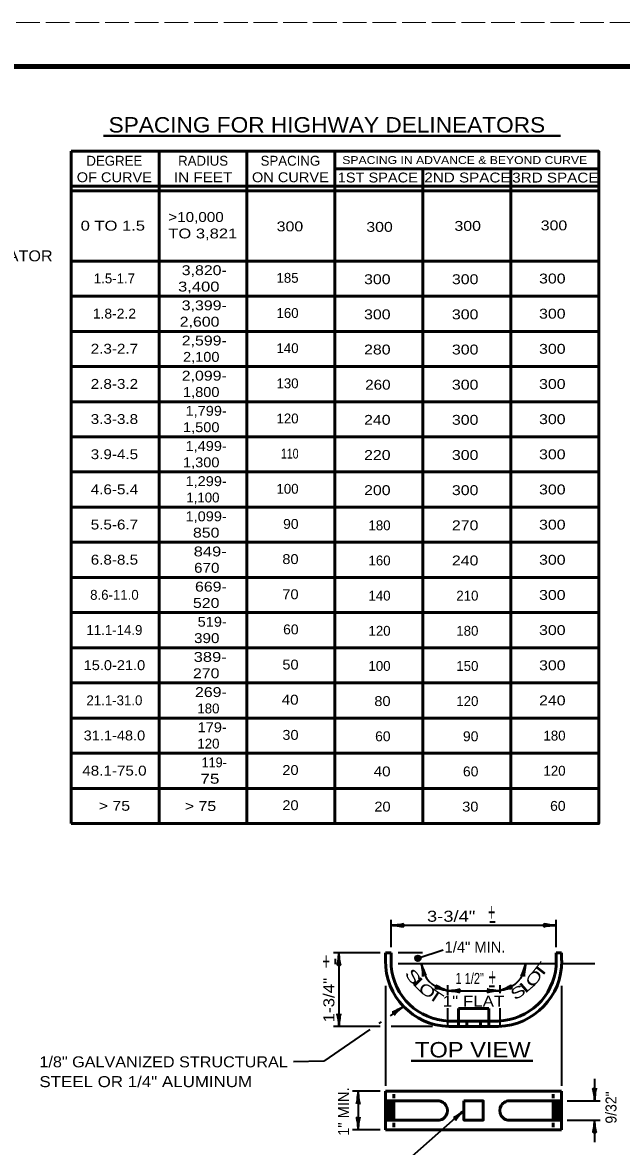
# Model space of a CAD drawing. Extents: x -54 to 626, y -41 to 399.
# Drawn here: x 331.9 to 468.1, y 142.9 to 398.7 of the extents above; entities that cross this region are included whole.
import ezdxf
from ezdxf.enums import TextEntityAlignment as Align

# ---------------------------------------------------------------- set-up
doc = ezdxf.new("R2010")
doc.units = 0
doc.header["$LTSCALE"] = 0.9
doc.linetypes.add('LONG_DASHED', pattern=[7.5, 6, -1.5])
doc.linetypes.add('MEDIUM_DASHED', pattern=[4.5, 3, -1.5])
doc.layers.add('1', color=7, linetype='Continuous', lineweight=35)
doc.layers.add('61', color=7, linetype='Continuous', lineweight=35)

msp = doc.modelspace()

# ---------------------------------------------------------------- hatches: boundary and pattern name
at = {"layer": '1'}
msp.add_hatch(color=256, dxfattribs=at).paths.add_polyline_path([(422.3962, 185.7724, 1), (421.1462, 185.7724, 1)])

# ---------------------------------------------------------------- linework, layer by layer
at = {"layer": '1', "lineweight": 40}
for p, q in [((350.2797, 372.8977), (454.1692, 372.8977)), ((420.1955, 162.4636), (447.8977, 162.4636))]:
    msp.add_line(p, q, dxfattribs=at)
at = {"layer": '1', "lineweight": 53}
for p, q in [((342.8963, 360.4209), (342.8963, 369.4209)), ((362.8963, 216.4209), (362.8963, 369.4209)), ((382.8963, 216.4209), (382.8963, 369.4209)), ((402.8963, 216.4209), (402.8963, 369.4209)), ((402.8963, 365.4209), (462.8963, 365.4209)), ((422.8963, 216.4209), (422.8963, 365.4209)), ((442.8963, 216.4209), (442.8963, 365.4209)), ((342.8963, 361.4209), (462.8963, 361.4209)), ((342.8963, 360.4209), (462.8963, 360.4209)), ((342.8963, 344.4209), (462.8963, 344.4209)), ((342.8963, 336.4209), (462.8963, 336.4209)), ((342.8963, 328.4209), (462.8963, 328.4209)), ((342.8963, 320.4209), (462.8963, 320.4209)), ((342.8963, 312.4209), (462.8963, 312.4209)), ((342.8963, 304.4209), (462.8963, 304.4209)), ((342.8963, 296.4209), (462.8963, 296.4209)), ((342.8963, 288.4209), (462.8963, 288.4209)), ((342.8963, 280.4209), (462.8963, 280.4209)), ((342.8963, 272.4209), (462.8963, 272.4209)), ((342.8963, 264.4209), (462.8963, 264.4209)), ((342.8963, 256.4209), (462.8963, 256.4209)), ((342.8963, 248.4209), (462.8963, 248.4209)), ((342.8963, 240.4209), (462.8963, 240.4209)), ((342.8963, 232.4209), (462.8963, 232.4209)), ((342.8963, 224.4209), (462.8963, 224.4209)), ((414.4306, 187.0178), (414.4306, 185.2447)), ((414.4306, 187.0178), (415.6806, 187.0178)), ((415.6806, 187.0178), (415.6806, 183.9947)), ((453.1806, 187.0178), (453.1806, 183.9947)), ((453.1806, 187.0178), (454.4306, 187.0178)), ((454.4306, 187.0178), (454.4306, 185.2447)), ((430.9931, 174.3072), (430.9931, 170.2447)), ((430.9931, 174.3072), (437.8681, 174.3072)), ((437.8681, 174.3072), (437.8681, 170.2447)), ((428.8056, 171.4947), (440.0556, 171.4947)), ((428.8056, 170.2447), (440.0556, 170.2447)), ((414.4306, 155.4938), (454.4306, 155.4938)), ((414.4306, 155.4938), (414.4306, 153.3063)), ((416.3056, 154.8688), (416.3056, 153.9313)), ((452.5556, 154.8688), (452.5556, 153.9313)), ((454.4306, 155.4938), (454.4306, 153.3063)), ((414.4306, 152.9551), (414.7818, 153.3063)), ((414.4306, 152.0712), (415.6658, 153.3063)), ((414.4306, 151.1873), (416.3056, 153.0623)), ((414.4306, 150.3034), (416.3056, 152.1784)), ((414.4306, 149.4195), (416.3056, 151.2945)), ((416.3056, 153.3063), (416.3056, 148.9313)), ((416.3056, 153.3063), (425.9931, 153.3063)), ((416.3056, 153.3063), (416.3056, 148.9313)), ((452.5556, 148.9313), (452.5556, 153.3063)), ((452.5556, 153.3063), (452.5556, 148.9313)), ((454.4306, 151.1204), (452.5556, 152.9954)), ((454.4306, 150.2366), (452.5556, 152.1116)), ((454.4306, 149.3527), (452.5556, 151.2277)), ((454.4306, 152.0042), (453.1285, 153.3063)), ((454.4306, 152.8882), (454.0125, 153.3063)), ((414.4306, 148.9313), (414.4306, 146.7438)), ((425.9931, 148.9313), (414.4306, 148.9313)), ((414.8263, 148.9313), (416.3056, 150.4107)), ((415.7102, 148.9313), (416.3056, 149.5267)), ((453.968, 148.9313), (452.5556, 150.3438)), ((453.0842, 148.9313), (452.5556, 149.4599)), ((454.4306, 148.9313), (454.4306, 146.7438)), ((414.4306, 146.7438), (454.4306, 146.7438)), ((416.3056, 148.3063), (416.3056, 147.3688)), ((452.5556, 148.3063), (452.5556, 147.3688))]:
    msp.add_line(p, q, dxfattribs=at)
at = {"layer": '1'}
for p, q in [((415.6806, 188.2678), (415.6806, 194.5178)), ((453.1806, 188.2678), (453.1806, 194.5178)), ((415.6806, 193.2678), (453.1806, 193.2678)), ((413.1806, 187.0178), (402.5556, 187.0178)), ((403.8056, 187.0178), (403.8056, 170.2447)), ((417.2431, 187.0563), (422.7978, 187.0563)), ((421.7713, 185.7724), (427.4873, 187.7001)), ((417.2431, 184.5563), (453.1806, 184.5563)), ((454.4659, 184.5563), (461.9659, 184.5563)), ((414.4306, 179.5178), (414.4306, 156.7438)), ((428.4931, 179.6197), (428.4931, 177.4076)), ((440.3681, 179.6197), (440.3681, 177.8185)), ((454.4306, 179.5178), (454.4306, 156.7438)), ((428.4931, 178.3697), (440.3681, 178.3697)), ((418.5205, 174.8172), (415.46, 172.7092)), ((428.4931, 174.3814), (428.4931, 171.8072)), ((440.3681, 174.3814), (440.3681, 171.8072)), ((410.8521, 169.5355), (400.3792, 162.3222)), ((413.1806, 170.2447), (402.5556, 170.2447)), ((413.401, 171.2911), (412.9111, 170.9537)), ((425.0556, 170.2447), (415.6806, 170.2447)), ((428.4931, 171.1822), (428.4931, 170.5572)), ((440.3681, 171.1822), (440.3681, 170.5572)), ((400.3792, 162.3222), (393.5135, 162.2342)), ((461.9306, 158.3063), (461.9306, 153.3063)), ((413.1806, 155.4938), (406.9306, 155.4938)), ((408.1806, 155.4938), (408.1806, 146.7438)), ((455.6806, 153.3063), (463.1806, 153.3063)), ((455.6806, 148.9313), (463.1806, 148.9313)), ((461.9306, 148.9313), (461.9306, 143.9313)), ((413.1806, 146.7438), (406.9306, 146.7438))]:
    msp.add_line(p, q, dxfattribs=at)
at = {"layer": '1', "linetype": 'MEDIUM_DASHED', "lineweight": 53}
for p, q in [((432.8681, 171.4947), (432.8681, 170.2447)), ((435.9931, 171.4947), (435.9931, 170.2447))]:
    msp.add_line(p, q, dxfattribs=at)
at = {"layer": '1', "lineweight": 53}
for points in [[(342.8963, 369.4209), (462.8963, 369.4209), (462.8963, 216.4209), (342.8963, 216.4209)], [(342.8963, 216.4209), (342.8963, 344.4209), (342.8963, 360.4209)], [(414.4306, 148.9313), (414.4306, 153.3063), (425.9931, 153.3063)], [(425.9931, 148.9313), (416.3056, 148.9313), (416.3056, 153.3063)], [(442.8681, 153.3063), (454.4306, 153.3063), (454.4306, 148.9313), (442.8681, 148.9313)], [(442.8681, 148.9313), (452.5556, 148.9313), (452.5556, 153.3063), (442.8681, 153.3063)]]:
    msp.add_lwpolyline(points, dxfattribs=at)
at = {"layer": '1'}
msp.add_lwpolyline([(432.2431, 151.1188), (420.4005, 140.6441), (406.0473, 140.6441)], dxfattribs=at)
at = {"layer": '1', "lineweight": 53}
msp.add_lwpolyline([(432.2431, 153.3063), (432.2431, 148.9313), (436.6181, 148.9313), (436.6181, 153.3063)], close=True, dxfattribs=at)
at = {"layer": '1'}
msp.add_circle((421.7712, 185.7724), 0.625, dxfattribs=at)
at = {"layer": '1', "lineweight": 53}
for centre, radius, start, end in [((429.2552, 185.1074), 14.8701, 179.46942, 268.10829), ((439.606, 185.1074), 14.8701, 271.89171, 0.53058), ((429.2552, 185.1074), 13.6201, 184.68607, 268.10829), ((439.606, 185.1074), 13.6201, 271.89171, 355.31393), ((426.2861, 151.1189), 2.207, 262.37185, 97.62815), ((426.2861, 151.1189), 2.207, 262.37185, 97.62815), ((442.5751, 151.1189), 2.207, 82.37185, 277.62815), ((442.5751, 151.1189), 2.207, 82.37185, 277.62815)]:
    msp.add_arc(centre, radius, start, end, dxfattribs=at)
at = {"layer": '1'}
for centre, start, end in [((429.2552, 185.1074), 198.64913, 263.51251), ((439.606, 185.1074), 276.48749, 341.85662)]:
    msp.add_arc(centre, 6.7451, start, end, dxfattribs=at)
at = {"layer": '1', "lineweight": 40}
for centre, major_axis, ratio, start_param, end_param in [((416.8011, 193.0562), (-1.7565, 0.1757), 0.07063, 3.14071475, 5.41810995), ((416.7718, 193.5441), (-1.7857, -0.1562), 0.122415, 0.89635335, 3.14159265), ((452.0894, 192.9915), (1.7857, 0.1562), 0.122415, 0.89635335, 3.14159265), ((452.0894, 192.9915), (1.7857, 0.1562), 0.122415, 0.89635335, 3.14159265), ((452.0601, 193.4794), (1.7565, -0.1757), 0.07063, 3.14071475, 5.41810995), ((452.0601, 193.4794), (1.7565, -0.1757), 0.07063, 3.14071475, 5.41810995), ((403.594, 185.8973), (0.1757, 1.7565), 0.07063, 3.14071475, 5.41810995), ((403.594, 185.8973), (0.1757, 1.7565), 0.07063, 3.14071475, 5.41810995), ((404.0819, 185.9266), (-0.1562, 1.7857), 0.122415, 0.89635335, 3.14159265), ((404.0819, 185.9266), (-0.1562, 1.7857), 0.122415, 0.89635335, 3.14159265), ((422.552, 183.4241), (-0.3017, 1.7669), 0.122415, 3.14159265, 5.38683196), ((423.0314, 183.5194), (0.6152, -1.6545), 0.07063, 4.00666801, 6.28406321), ((445.8298, 183.5194), (-0.6152, -1.6545), 0.07063, 6.28230741, 8.55970261), ((446.3091, 183.4241), (0.3017, 1.7669), 0.122415, 0.89635335, 3.14159265), ((427.5275, 178.997), (1.6525, -0.6944), 0.122415, 3.14159265, 5.38683196), ((441.3336, 178.997), (-1.6525, -0.6944), 0.122415, 0.89635335, 3.14159265), ((427.3505, 178.5414), (1.7261, -0.3696), 0.07063, 0.86507535, 3.14247055), ((429.6136, 178.1581), (-1.7565, 0.1757), 0.07063, 3.14071475, 5.41810995), ((429.6136, 178.1581), (-1.7565, 0.1757), 0.07063, 3.14071475, 5.41810995), ((429.5843, 178.646), (-1.7857, -0.1562), 0.122415, 0.89635335, 3.14159265), ((429.5843, 178.646), (-1.7857, -0.1562), 0.122415, 0.89635335, 3.14159265), ((439.2769, 178.0934), (1.7857, 0.1562), 0.122415, 0.89635335, 3.14159265), ((439.2769, 178.0934), (1.7857, 0.1562), 0.122415, 0.89635335, 3.14159265), ((439.2476, 178.5813), (1.7565, -0.1757), 0.07063, 3.14071475, 5.41810995), ((439.2476, 178.5813), (1.7565, -0.1757), 0.07063, 3.14071475, 5.41810995), ((441.5107, 178.5414), (-1.7261, -0.3696), 0.07063, 3.14071475, 5.41810995), ((417.4777, 174.3558), (1.5462, 0.8517), 0.07063, 3.14071475, 5.41810995), ((417.4777, 174.3558), (1.5462, 0.8517), 0.07063, 3.14071475, 5.41810995), ((417.7786, 173.9706), (1.382, 1.1415), 0.122415, 0.89635335, 3.14159265), ((417.7786, 173.9706), (1.382, 1.1415), 0.122415, 0.89635335, 3.14159265), ((403.5293, 171.3359), (0.1562, -1.7857), 0.122415, 0.89635335, 3.14159265), ((403.5293, 171.3359), (0.1562, -1.7857), 0.122415, 0.89635335, 3.14159265), ((404.0172, 171.3652), (-0.1757, -1.7565), 0.07063, 3.14071475, 5.41810995), ((404.0172, 171.3652), (-0.1757, -1.7565), 0.07063, 3.14071475, 5.41810995), ((461.6543, 154.3975), (0.1562, -1.7857), 0.122415, 0.89635335, 3.14159265), ((462.1422, 154.4268), (-0.1757, -1.7565), 0.07063, 3.14071475, 5.41810995), ((407.969, 154.3733), (0.1757, 1.7565), 0.07063, 3.14071475, 5.41810995), ((407.969, 154.3733), (0.1757, 1.7565), 0.07063, 3.14071475, 5.41810995), ((408.4569, 154.4026), (-0.1562, 1.7857), 0.122415, 0.89635335, 3.14159265), ((408.4569, 154.4026), (-0.1562, 1.7857), 0.122415, 0.89635335, 3.14159265), ((431.2636, 150.535), (-1.432, -1.0321), 0.07063, 6.28230741, 8.55970261), ((431.2636, 150.535), (-1.432, -1.0321), 0.07063, 6.28230741, 8.55970261), ((431.6088, 150.1889), (1.2341, 1.3), 0.122415, 0.89635335, 3.14159265), ((431.6088, 150.1889), (1.2341, 1.3), 0.122415, 0.89635335, 3.14159265), ((407.9043, 147.835), (0.1562, -1.7857), 0.122415, 0.89635335, 3.14159265), ((408.3922, 147.8643), (-0.1757, -1.7565), 0.07063, 3.14071475, 5.41810995), ((461.719, 147.8108), (0.1757, 1.7565), 0.07063, 3.14071475, 5.41810995), ((462.2069, 147.8401), (-0.1562, 1.7857), 0.122415, 0.89635335, 3.14159265)]:
    msp.add_ellipse(centre, major_axis=major_axis, ratio=ratio, start_param=start_param, end_param=end_param, dxfattribs=at)
at = {"layer": '61', "linetype": 'LONG_DASHED', "lineweight": 13}
msp.add_line((-54.3422, 398.7039), (625.6777, 398.7039), dxfattribs=at)
at = {"layer": '61', "lineweight": 158}
msp.add_lwpolyline([(614.6977, 388.7039), (-24.3422, 388.7039), (-24.3422, -31.3161)], dxfattribs=at)

# ---------------------------------------------------------------- texts
at = {"layer": '1'}
for s, height, width, p in [('SPACING FOR HIGHWAY DELINEATORS', 3.5, 1.1, (351.4363, 373.6691)), ('SPACING IN ADVANCE & BEYOND CURVE', 1.8, 1.15, (404.5719, 366.4957)), ('1ST SPACE', 2.25, 1.1, (403.5457, 362.3012)), ('2ND SPACE', 2.25, 1.15, (423.2246, 362.3012)), ('3RD SPACE', 2.25, 1.15, (443.2062, 362.2888)), ('>10,000', 2.25, 1.15, (365.0087, 353.3171)), ('0 TO 1.5', 2.25, 1.25, (345.0831, 351.3374)), ('300', 2.25, 1.2, (389.6567, 351.1799)), ('300', 2.25, 1.2, (410.0303, 351.0683)), ('300', 2.25, 1.2, (430.0775, 351.2934)), ('300', 2.25, 1.2, (449.6923, 351.4029)), ('TO 3,821', 2.25, 1.25, (365.0087, 349.5671)), ('HOUSED DELINEATOR', 2.5, 1.1, (298.4603, 344.3497)), ('> 75', 2.25, 1.2, (368.7681, 219.2754)), ('+', 4, 0.55, (437.6743, 194.2944)), ('3-3/4"', 2.5, 1.25, (423.8171, 194.0838)), ('+', 4, 0.55, (400.0276, 183.0864)), ('1 1/2"', 2.5, 0.75, (430.3054, 179.9348)), ('+', 4, 0.55, (437.8237, 179.4998)), ('1" FLAT', 2.5, 1.15, (427.4332, 174.7533)), ('TOP VIEW', 3.5, 1.15, (421.0918, 163.2108)), ('1/8" GALVANIZED STRUCTURAL', 2.5, 1.1, (335.7058, 160.9491)), ('STEEL OR 1/4" ALUMINUM', 2.5, 1.15, (335.7058, 156.4491))]:
    msp.add_text(s, height=height, dxfattribs=dict(at, width=width)).set_placement(p)
for s, p in [('DEGREE', (352.7375, 366.1142)), ('RADIUS', (372.9246, 366.1142)), ('SPACING', (392.7717, 366.1142)), ('1.5-1.7', (352.7591, 339.3398)), ('8.6-11.0', (352.7592, 267.3398)), ('11.1-14.9', (352.7592, 259.3398)), ('21.1-31.0', (352.7591, 243.3398))]:
    msp.add_text(s, height=2.25, dxfattribs=at).set_placement(p, align=Align.CENTER)
for s, width, p in [('OF CURVE', 1.1, (352.7374, 362.3642)), ('IN FEET', 1.15, (372.9246, 362.3642)), ('ON CURVE', 1.1, (392.7717, 362.3642)), ('1.8-2.2', 1.05, (352.7592, 331.3398)), ('2.3-2.7', 1.15, (352.7592, 323.3398)), ('2.8-3.2', 1.15, (352.7591, 315.3398)), ('3.3-3.8', 1.15, (352.7591, 307.3398)), ('3.9-4.5', 1.15, (352.7591, 299.3398)), ('4.6-5.4', 1.15, (352.7592, 291.3398)), ('5.5-6.7', 1.15, (352.7592, 283.3398)), ('6.8-8.5', 1.15, (352.7591, 275.3398)), ('15.0-21.0', 1.1, (352.7591, 251.3398)), ('31.1-48.0', 1.1, (352.7591, 235.3398)), ('48.1-75.0', 1.15, (352.7592, 227.3398)), ('> 75', 1.2, (352.7591, 219.3398))]:
    msp.add_text(s, height=2.25, dxfattribs=dict(at, width=width)).set_placement(p, align=Align.CENTER)
for s, width, p in [('3,820-', 1.2, (378.3072, 341.2116)), ('300', 1.2, (415.5486, 339.1591)), ('300', 1.2, (435.522, 339.1591)), ('300', 1.2, (455.3382, 339.3164)), ('3,400', 1.25, (376.6421, 337.4894)), ('3,399-', 1.2, (378.3071, 333.2116)), ('300', 1.2, (415.5486, 331.1591)), ('300', 1.2, (435.522, 331.1591)), ('300', 1.2, (455.3382, 331.3164)), ('2,600', 1.2, (376.6421, 329.4894)), ('2,599-', 1.2, (378.3071, 325.2116)), ('280', 1.2, (415.5486, 323.1591)), ('300', 1.2, (435.522, 323.1591)), ('300', 1.2, (455.3382, 323.3164)), ('2,100', 1.1, (376.6421, 321.4894)), ('2,099-', 1.2, (378.3071, 317.2116)), ('260', 1.15, (415.5486, 315.1591)), ('300', 1.2, (435.522, 315.1591)), ('300', 1.2, (455.3382, 315.3164)), ('1,800', 1.1, (376.6421, 313.4894)), ('1,799-', 1.1, (378.3071, 309.2116)), ('300', 1.2, (455.3382, 307.3164)), ('1,500', 1.1, (376.6421, 305.4894)), ('240', 1.2, (415.5485, 307.1591)), ('300', 1.2, (435.522, 307.1591)), ('1,499-', 1.1, (378.3072, 301.2116)), ('1,300', 1.1, (376.6421, 297.4894)), ('110', 0.8, (394.6314, 299.4737)), ('220', 1.2, (415.5486, 299.1591)), ('300', 1.2, (435.522, 299.1591)), ('300', 1.2, (455.3382, 299.3164)), ('1,299-', 1.1, (378.3071, 293.2116)), ('200', 1.2, (415.5486, 291.1591)), ('300', 1.2, (435.522, 291.1591)), ('300', 1.2, (455.3382, 291.3164)), ('1,099-', 1.1, (378.3071, 285.2116)), ('90', 1.05, (394.6314, 283.4737)), ('270', 1.2, (435.522, 283.1591)), ('300', 1.2, (455.3382, 283.3164)), ('850', 1.2, (376.6421, 281.4894)), ('849-', 1.25, (378.3072, 277.2116)), ('80', 1.1, (394.6313, 275.4737)), ('240', 1.2, (435.5219, 275.1591)), ('300', 1.2, (455.3382, 275.3164)), ('670', 1.15, (376.642, 273.4894)), ('669-', 1.2, (378.3071, 269.2116)), ('70', 1.1, (394.6313, 267.4737)), ('300', 1.2, (455.3382, 267.3164)), ('520', 1.2, (376.6421, 265.4894)), ('519-', 1.1, (378.3072, 261.2116)), ('60', 1.05, (394.6314, 259.4737)), ('300', 1.2, (455.3382, 259.3164)), ('390', 1.15, (376.6421, 257.4894)), ('389-', 1.25, (378.3071, 253.2116)), ('50', 1.1, (394.6313, 251.4737)), ('300', 1.2, (455.3382, 251.3164)), ('270', 1.2, (376.6421, 249.4894)), ('269-', 1.2, (378.3072, 245.2116)), ('40', 1.15, (394.6314, 243.4737)), ('240', 1.2, (455.3382, 243.3164)), ('80', 1.1, (415.5485, 243.1591)), ('179-', 1.1, (378.3071, 237.2116)), ('30', 1.1, (394.6313, 235.4737)), ('60', 1.05, (415.5486, 235.1591)), ('90', 1.05, (435.522, 235.1591)), ('119-', 0.95, (378.3072, 229.2116)), (' 75', 1.3, (376.642, 225.4894)), ('20', 1.1, (394.6313, 227.4737)), ('40', 1.15, (415.5486, 227.1591)), ('60', 1.05, (435.522, 227.1591)), ('20', 1.1, (394.6313, 219.4737)), ('20', 1.1, (415.5485, 219.1591)), ('30', 1.1, (435.5219, 219.1591)), ('60', 1.05, (455.3382, 219.3164))]:
    msp.add_text(s, height=2.25, dxfattribs=dict(at, width=width)).set_placement(p, align=Align.RIGHT)
for s, p in [('185', (394.6313, 339.4737)), ('160', (394.6314, 331.4737)), ('140', (394.6314, 323.4737)), ('130', (394.6313, 315.4737)), ('120', (394.6313, 307.4737)), ('1,100', (376.6421, 289.4894)), ('100', (394.6313, 291.4737)), ('180', (415.5485, 283.1591)), ('160', (415.5486, 275.1591)), ('140', (415.5486, 267.1591)), ('210', (435.5219, 267.1591)), ('120', (415.5485, 259.1591)), ('180', (435.5219, 259.1591)), ('100', (415.5485, 251.1591)), ('150', (435.5219, 251.1591)), ('180', (376.642, 241.4894)), ('120', (435.5219, 243.1591)), ('120', (376.642, 233.4894)), ('180', (455.3382, 235.3164)), ('120', (455.3382, 227.3164))]:
    msp.add_text(s, height=2.25, dxfattribs=at).set_placement(p, align=Align.RIGHT)
for s, height, p in [('-', 4, (437.8237, 192.5012)), ('1/4" MIN.', 2.5, (427.8398, 187.0743)), ('-', 4, (437.6743, 177.856))]:
    msp.add_text(s, height=height, dxfattribs=at).set_placement(p)
for s, height, p in [('-', 4, (404.5093, 184.1325)), ('1" MIN.', 2.5, (406.1162, 145.3657))]:
    msp.add_text(s, height=height, rotation=90, dxfattribs=at).set_placement(p)
for s, rotation, width, p in [('T', 51.983, 1.8, (449.4983, 180.8291)), ('S', 306.861, 1.6, (418.5948, 182.2728)), ('O', 51.629, 1.5, (447.8951, 178.9063)), ('1-3/4"', 90, 1.15, (402.7692, 171.1736)), ('L', 315.068, 2.1, (420.2163, 180.1279)), ('O', 325.945, 1.4, (421.6664, 178.4151)), ('S', 32.545, 1.45, (443.8172, 176.1337)), ('L', 40.753, 1.9, (446.078, 177.5892)), ('T', 326.299, 1.65, (423.7043, 176.9611)), ('9/32"', 90, 0.95, (466.9193, 148.1558))]:
    msp.add_text(s, height=2.5, rotation=rotation, dxfattribs=dict(at, width=width)).set_placement(p)

doc.saveas('drawing.dxf')
